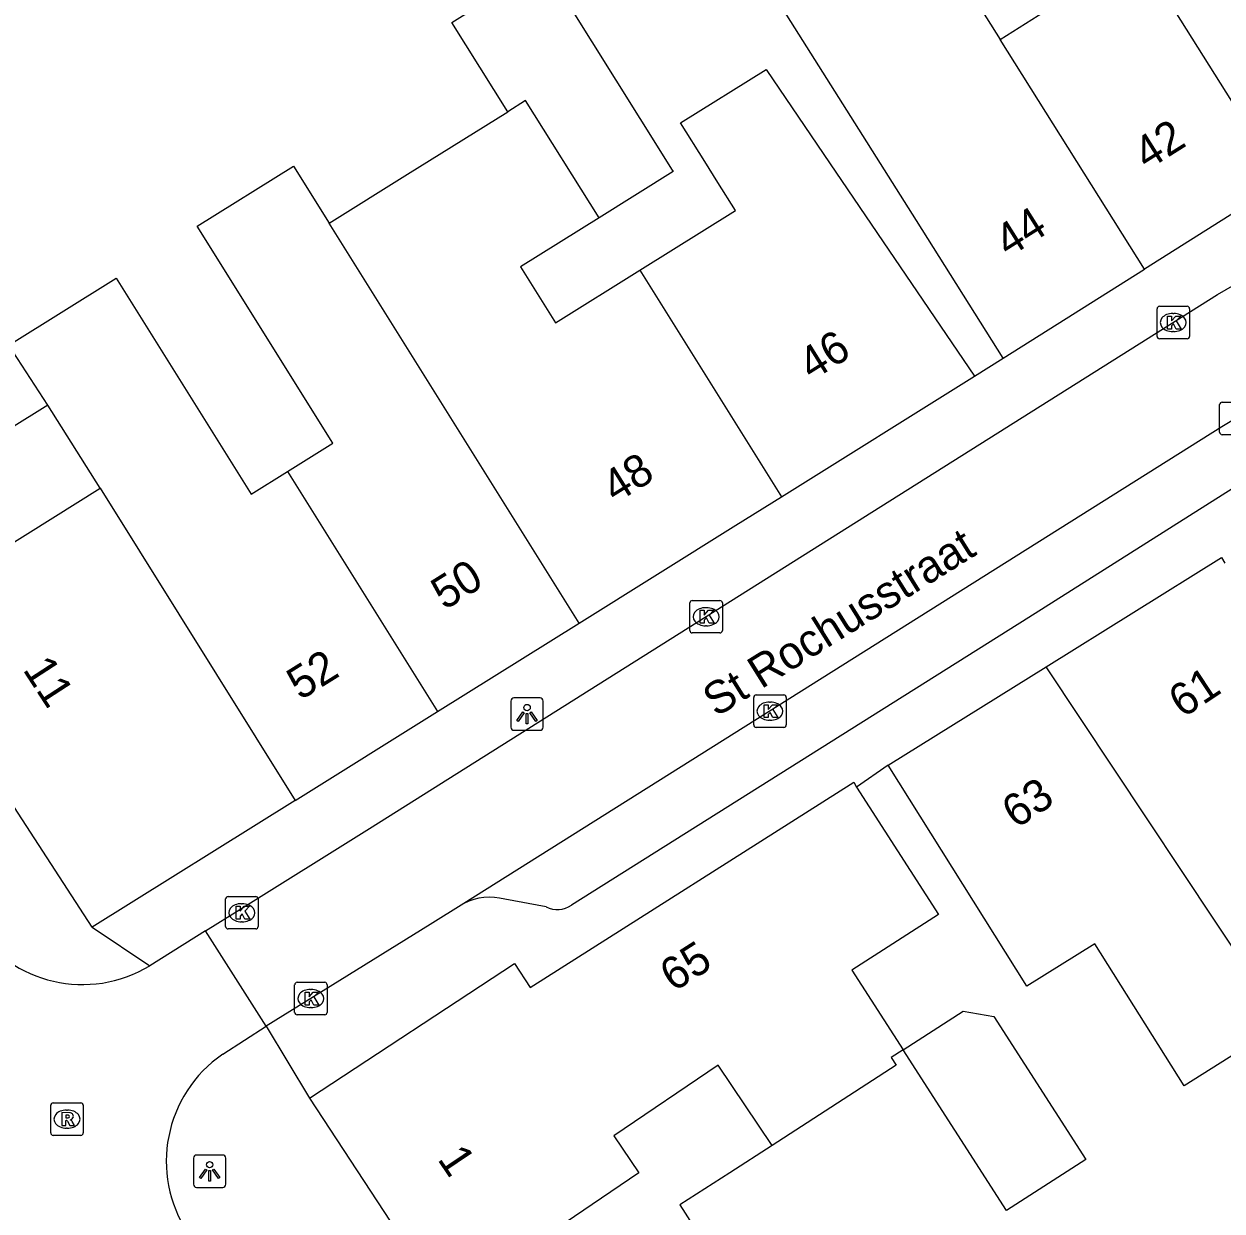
# Model space of a CAD drawing. Extents: x 161801 to 162379, y 382315 to 382832.
# Drawn here: x 161942.5 to 161979.42, y 382498.82 to 382535.41 of the extents above; entities that cross this region are included whole.
import ezdxf

# ---------------------------------------------------------------- set-up
doc = ezdxf.new("R2010")
doc.units = 0
for name, color, linetype in [('IMGEO_Kolk', 7, 'Continuous'), ('IMGEO_Lichtpunt', 7, 'Continuous'), ('IMGEO_Openbare_ruimte_label', 7, 'Continuous'), ('IMGEO_Pand', 7, 'Continuous'), ('IMGEO_Pand_nummerreeks', 7, 'Continuous'), ('IMGEO_Rijbaan_lokaal_open', 7, 'Continuous'), ('IMGEO_Rioolput', 7, 'Continuous'), ('IMGEO_Voetpad_open', 7, 'Continuous')]:
    doc.layers.add(name, color=color, linetype=linetype)

msp = doc.modelspace()

# ---------------------------------------------------------------- linework, layer by layer
at = {"layer": 'IMGEO_Kolk'}
for p, q in [((161977.413, 382525.777), (161977.413, 382526.629)), ((161977.488, 382526.703), (161978.34, 382526.703)), ((161978.414, 382526.629), (161978.414, 382525.777)), ((161977.901, 382526.483), (161977.926, 382526.483)), ((161977.924, 382525.923), (161977.899, 382525.923)), ((161978.34, 382525.703), (161977.488, 382525.703)), ((161979.341, 382522.821), (161979.341, 382523.673)), ((161979.416, 382523.747), (161980.268, 382523.747)), ((161980.268, 382522.747), (161979.416, 382522.747)), ((161963.092, 382517.636), (161963.944, 382517.636)), ((161963.017, 382516.71), (161963.017, 382517.562)), ((161963.505, 382517.416), (161963.53, 382517.416)), ((161964.018, 382517.562), (161964.018, 382516.71)), ((161963.944, 382516.636), (161963.092, 382516.636)), ((161963.528, 382516.856), (161963.503, 382516.856)), ((161965.06, 382514.726), (161965.912, 382514.726)), ((161964.985, 382513.8), (161964.985, 382514.652)), ((161965.473, 382514.506), (161965.498, 382514.506)), ((161965.986, 382514.652), (161965.986, 382513.8)), ((161965.496, 382513.946), (161965.471, 382513.946)), ((161965.912, 382513.726), (161965.06, 382513.726)), ((161948.712, 382507.587), (161948.712, 382508.439)), ((161948.787, 382508.513), (161949.639, 382508.513)), ((161949.713, 382508.439), (161949.713, 382507.587)), ((161949.2, 382508.293), (161949.225, 382508.293)), ((161949.223, 382507.733), (161949.198, 382507.733)), ((161949.639, 382507.513), (161948.787, 382507.513)), ((161950.914, 382505.87), (161951.766, 382505.87)), ((161950.839, 382504.944), (161950.839, 382505.796)), ((161951.327, 382505.65), (161951.352, 382505.65)), ((161951.84, 382505.796), (161951.84, 382504.944)), ((161951.35, 382505.09), (161951.325, 382505.09)), ((161951.766, 382504.87), (161950.914, 382504.87))]:
    msp.add_line(p, q, dxfattribs=at)
for points in [[(161977.413, 382525.777), (161977.413, 382526.629)], [(161977.488, 382526.703), (161978.34, 382526.703)], [(161978.414, 382526.629), (161978.414, 382525.777)], [(161977.734, 382526.403), (161977.857, 382526.403), (161977.857, 382526.252), (161977.987, 382526.403), (161978.151, 382526.403), (161978.005, 382526.252), (161978.158, 382526.003), (161978.006, 382526.003), (161977.921, 382526.167), (161977.857, 382526.1), (161977.857, 382526.003), (161977.734, 382526.003), (161977.734, 382526.403)], [(161978.34, 382525.703), (161977.488, 382525.703)], [(161979.341, 382522.821), (161979.341, 382523.673)], [(161979.416, 382523.747), (161980.268, 382523.747)], [(161980.268, 382522.747), (161979.416, 382522.747)], [(161963.092, 382517.636), (161963.944, 382517.636)], [(161963.017, 382516.71), (161963.017, 382517.562)], [(161963.338, 382517.336), (161963.461, 382517.336), (161963.461, 382517.185), (161963.591, 382517.336), (161963.755, 382517.336), (161963.609, 382517.185), (161963.762, 382516.936), (161963.61, 382516.936), (161963.525, 382517.1), (161963.461, 382517.033), (161963.461, 382516.936), (161963.338, 382516.936), (161963.338, 382517.336)], [(161964.018, 382517.562), (161964.018, 382516.71)], [(161963.944, 382516.636), (161963.092, 382516.636)], [(161965.06, 382514.726), (161965.912, 382514.726)], [(161964.985, 382513.8), (161964.985, 382514.652)], [(161965.306, 382514.426), (161965.429, 382514.426), (161965.429, 382514.275), (161965.559, 382514.426), (161965.723, 382514.426), (161965.577, 382514.275), (161965.73, 382514.026), (161965.578, 382514.026), (161965.493, 382514.19), (161965.429, 382514.123), (161965.429, 382514.026), (161965.306, 382514.026), (161965.306, 382514.426)], [(161965.986, 382514.652), (161965.986, 382513.8)], [(161965.912, 382513.726), (161965.06, 382513.726)], [(161948.712, 382507.587), (161948.712, 382508.439)], [(161948.787, 382508.513), (161949.639, 382508.513)], [(161949.713, 382508.439), (161949.713, 382507.587)], [(161949.033, 382508.213), (161949.156, 382508.213), (161949.156, 382508.062), (161949.286, 382508.213), (161949.45, 382508.213), (161949.304, 382508.062), (161949.457, 382507.813), (161949.305, 382507.813), (161949.22, 382507.977), (161949.156, 382507.91), (161949.156, 382507.813), (161949.033, 382507.813), (161949.033, 382508.213)], [(161949.639, 382507.513), (161948.787, 382507.513)], [(161950.914, 382505.87), (161951.766, 382505.87)], [(161950.839, 382504.944), (161950.839, 382505.796)], [(161951.16, 382505.57), (161951.283, 382505.57), (161951.283, 382505.419), (161951.413, 382505.57), (161951.577, 382505.57), (161951.431, 382505.419), (161951.584, 382505.17), (161951.432, 382505.17), (161951.347, 382505.334), (161951.283, 382505.267), (161951.283, 382505.17), (161951.16, 382505.17), (161951.16, 382505.57)], [(161951.84, 382505.796), (161951.84, 382504.944)], [(161951.766, 382504.87), (161950.914, 382504.87)]]:
    msp.add_lwpolyline(points, dxfattribs=at)
for centre, start, end in [((161977.49, 382526.627), 91.552, 178.448), ((161977.49, 382526.627), 91.552, 178.448), ((161978.338, 382526.627), 1.552, 88.448), ((161978.338, 382526.627), 1.552, 88.448), ((161977.49, 382525.779), 181.552, 268.448), ((161977.49, 382525.779), 181.552, 268.448), ((161978.338, 382525.779), 271.552, 358.448), ((161978.338, 382525.779), 271.552, 358.448), ((161979.418, 382523.671), 91.552, 178.448), ((161979.418, 382523.671), 91.552, 178.448), ((161979.418, 382522.823), 181.552, 268.448), ((161979.418, 382522.823), 181.552, 268.448), ((161963.094, 382517.56), 91.552, 178.448), ((161963.094, 382517.56), 91.552, 178.448), ((161963.942, 382517.56), 1.552, 88.448), ((161963.942, 382517.56), 1.552, 88.448), ((161963.094, 382516.712), 181.552, 268.448), ((161963.094, 382516.712), 181.552, 268.448), ((161963.942, 382516.712), 271.552, 358.448), ((161963.942, 382516.712), 271.552, 358.448), ((161965.062, 382514.65), 91.552, 178.448), ((161965.062, 382514.65), 91.552, 178.448), ((161965.91, 382514.65), 1.552, 88.448), ((161965.91, 382514.65), 1.552, 88.448), ((161965.062, 382513.802), 181.552, 268.448), ((161965.062, 382513.802), 181.552, 268.448), ((161965.91, 382513.802), 271.552, 358.448), ((161965.91, 382513.802), 271.552, 358.448), ((161948.789, 382508.437), 91.552, 178.448), ((161948.789, 382508.437), 91.552, 178.448), ((161949.637, 382508.437), 1.552, 88.448), ((161949.637, 382508.437), 1.552, 88.448), ((161948.789, 382507.589), 181.552, 268.448), ((161948.789, 382507.589), 181.552, 268.448), ((161949.637, 382507.589), 271.552, 358.448), ((161949.637, 382507.589), 271.552, 358.448), ((161950.916, 382505.794), 91.552, 178.448), ((161950.916, 382505.794), 91.552, 178.448), ((161951.764, 382505.794), 1.552, 88.448), ((161951.764, 382505.794), 1.552, 88.448), ((161950.916, 382504.946), 181.552, 268.448), ((161950.916, 382504.946), 181.552, 268.448), ((161951.764, 382504.946), 271.552, 358.448), ((161951.764, 382504.946), 271.552, 358.448)]:
    msp.add_arc(centre, 0.0765, start, end, dxfattribs=at)
for centre, major_axis, ratio, start_param, end_param in [((161977.9, 382526.203), (-0.387, 0.002), 0.722429, 4.712389, 7.853982), ((161977.925, 382526.203), (-0.39, 0.002), 0.717154, 1.570796, 4.712389), ((161963.504, 382517.136), (-0.387, 0.002), 0.722429, 4.712389, 7.853982), ((161963.529, 382517.136), (-0.39, 0.002), 0.717154, 1.570796, 4.712389), ((161965.472, 382514.226), (-0.387, 0.002), 0.722429, 4.712389, 7.853982), ((161965.497, 382514.226), (-0.39, 0.002), 0.717154, 1.570796, 4.712389), ((161949.199, 382508.013), (-0.387, 0.002), 0.722429, 4.712389, 7.853982), ((161949.224, 382508.013), (-0.39, 0.002), 0.717154, 1.570796, 4.712389), ((161951.326, 382505.37), (-0.387, 0.002), 0.722429, 4.712389, 7.853982), ((161951.351, 382505.37), (-0.39, 0.002), 0.717154, 1.570796, 4.712389)]:
    msp.add_ellipse(centre, major_axis=major_axis, ratio=ratio, start_param=start_param, end_param=end_param, dxfattribs=at)
at = {"layer": 'IMGEO_Lichtpunt'}
for p, q in [((161957.501, 382514.538), (161957.501, 382513.731)), ((161957.501, 382514.538), (161957.501, 382513.731)), ((161958.403, 382514.633), (161957.595, 382514.633)), ((161958.403, 382514.633), (161957.595, 382514.633)), ((161958.497, 382513.731), (161958.497, 382514.538)), ((161958.497, 382513.731), (161958.497, 382514.538)), ((161957.595, 382513.637), (161958.403, 382513.637)), ((161957.595, 382513.637), (161958.403, 382513.637)), ((161947.721, 382500.451), (161947.721, 382499.644)), ((161947.721, 382500.451), (161947.721, 382499.644)), ((161948.623, 382500.546), (161947.815, 382500.546)), ((161948.623, 382500.546), (161947.815, 382500.546)), ((161948.717, 382499.644), (161948.717, 382500.451)), ((161948.717, 382499.644), (161948.717, 382500.451)), ((161947.815, 382499.55), (161948.623, 382499.55)), ((161947.815, 382499.55), (161948.623, 382499.55))]:
    msp.add_line(p, q, dxfattribs=at)
for points in [[(161957.875, 382514.202), (161957.914, 382514.174), (161957.726, 382513.912), (161957.688, 382513.939), (161957.875, 382514.202)], [(161957.977, 382514.154), (161958.024, 382514.154), (161958.024, 382513.832), (161957.977, 382513.832), (161957.977, 382514.154)], [(161958.087, 382514.174), (161958.125, 382514.201), (161958.312, 382513.939), (161958.273, 382513.911), (161958.087, 382514.174)], [(161948.095, 382500.115), (161948.134, 382500.087), (161947.946, 382499.825), (161947.908, 382499.852), (161948.095, 382500.115)], [(161948.197, 382500.067), (161948.244, 382500.067), (161948.244, 382499.745), (161948.197, 382499.745), (161948.197, 382500.067)], [(161948.307, 382500.087), (161948.345, 382500.114), (161948.532, 382499.852), (161948.493, 382499.824), (161948.307, 382500.087)]]:
    msp.add_lwpolyline(points, dxfattribs=at)
for centre in [(161958, 382514.336), (161948.22, 382500.249)]:
    msp.add_circle(centre, 0.0994, dxfattribs=at)
for centre, start, end in [((161957.595, 382514.538), 90, 180), ((161957.595, 382514.538), 90, 180), ((161958.403, 382514.538), 0, 90), ((161958.403, 382514.538), 0, 90), ((161957.595, 382513.731), 180, 270), ((161957.595, 382513.731), 180, 270), ((161958.403, 382513.731), 270, 0), ((161958.403, 382513.731), 270, 360), ((161947.815, 382500.451), 90, 180), ((161947.815, 382500.451), 90, 180), ((161948.623, 382500.451), 0, 90), ((161948.623, 382500.451), 0, 90), ((161947.815, 382499.644), 180, 270), ((161947.815, 382499.644), 180, 270), ((161948.623, 382499.644), 270, 0), ((161948.623, 382499.644), 270, 360)]:
    msp.add_arc(centre, 0.0946, start, end, dxfattribs=at)
at = {"layer": 'IMGEO_Pand'}
for points in [[(161972.576, 382534.922), (161973.948, 382535.786), (161969.438, 382542.947), (161972.324, 382544.765)], [(161972.324, 382544.765), (161981.283, 382530.533)], [(161972.67, 382525.109), (161970, 382529.349), (161964.109, 382538.701), (161963.728, 382539.307), (161963.163, 382540.205), (161967.521, 382542.95), (161972.576, 382534.922)], [(161957.403, 382532.702), (161955.683, 382535.455), (161958.521, 382537.228), (161962.218, 382531.312), (161962.454, 382530.934), (161962.501, 382530.857), (161960.218, 382529.43)], [(161977.027, 382527.853), (161972.576, 382534.922)], [(161961.474, 382527.819), (161964.419, 382529.659), (161963.882, 382530.519), (161963.477, 382531.167), (161962.732, 382532.36), (161965.364, 382534.004), (161967.149, 382531.378), (161968.978, 382528.687), (161971.789, 382524.552)], [(161960.218, 382529.43), (161957.957, 382533.048), (161957.403, 382532.702)], [(161951.903, 382529.267), (161954.317, 382530.775), (161957.403, 382532.702)], [(161950.621, 382521.611), (161952.016, 382522.483), (161947.837, 382529.173), (161950.804, 382531.026), (161951.903, 382529.267)], [(161981.283, 382530.533), (161977.027, 382527.853)], [(161959.604, 382516.94), (161951.903, 382529.267)], [(161960.218, 382529.43), (161957.801, 382527.921), (161958.877, 382526.197), (161961.474, 382527.819)], [(161961.474, 382527.819), (161965.837, 382520.834)], [(161972.67, 382525.109), (161977.027, 382527.853)], [(161942.03, 382525.503), (161945.338, 382527.569), (161949.498, 382520.91), (161950.621, 382521.611)], [(161943.233, 382523.653), (161942.03, 382525.503)], [(161965.837, 382520.834), (161971.789, 382524.552)], [(161943.233, 382523.653), (161939.538, 382521.355)], [(161944.848, 382521.101), (161943.233, 382523.653)], [(161939.538, 382521.355), (161941.143, 382518.786), (161944.848, 382521.101)], [(161950.621, 382521.611), (161955.242, 382514.214)], [(161944.848, 382521.101), (161950.859, 382511.476)], [(161959.604, 382516.94), (161964.429, 382519.954), (161965.837, 382520.834)], [(161944.597, 382507.564), (161936.739, 382519.665)], [(161974, 382515.595), (161979.401, 382518.966), (161979.504, 382518.791)], [(161955.242, 382514.214), (161959.604, 382516.94)], [(161969.132, 382512.557), (161974, 382515.595)], [(161981.3, 382504.598), (161974, 382515.595)], [(161950.859, 382511.476), (161955.242, 382514.214)], [(161981.3, 382504.598), (161978.244, 382502.682), (161975.499, 382507.059), (161973.405, 382505.746), (161969.132, 382512.557)], [(161951.298, 382502.303), (161957.613, 382506.446), (161958.095, 382505.71), (161968.068, 382512.042), (161968.153, 382511.883)], [(161968.153, 382511.883), (161970.679, 382507.958), (161968.012, 382506.242), (161969.588, 382503.791)], [(161950.859, 382511.476), (161944.597, 382507.564)], [(161969.588, 382503.791), (161971.438, 382504.982), (161972.384, 382504.813), (161975.217, 382500.411), (161972.775, 382498.839), (161969.588, 382503.791)], [(161969.588, 382503.791), (161969.221, 382503.555), (161969.377, 382503.313), (161965.555, 382500.845)], [(161965.555, 382500.845), (161963.889, 382503.312), (161960.672, 382501.141), (161961.443, 382500.001), (161955.47, 382495.94)], [(161951.298, 382502.303), (161955.47, 382495.94)], [(161965.555, 382500.845), (161964.247, 382500), (161962.71, 382499.007), (161965.896, 382494.027)]]:
    msp.add_lwpolyline(points, dxfattribs=at)
at = {"layer": 'IMGEO_Rijbaan_lokaal_open'}
for points in [[(161948.095, 382507.457), (161949.145, 382508.117), (161953.15, 382510.607), (161979.276, 382527.063), (161985.491, 382530.651), (161991.203, 382533.931), (161998.314, 382537.876)], [(161996.967, 382533.235), (161986.125, 382527.031), (161979.411, 382522.988), (161956.057, 382508.297)], [(161956.057, 382508.297), (161955.014, 382507.648), (161949.963, 382504.519)], [(161948.095, 382507.457), (161946.38, 382506.38)], [(161949.963, 382504.519), (161948.095, 382507.457)], [(161948.623, 382503.653), (161949.963, 382504.519)]]:
    msp.add_lwpolyline(points, dxfattribs=at)
for centre, radius, start, end in [((161944.304, 382509.822), 4.02, 213.081, 301.0958), ((161950.883, 382500.352), 4, 124.3944, 213.4503)]:
    msp.add_arc(centre, radius, start, end, dxfattribs=at)
at = {"layer": 'IMGEO_Rioolput'}
for p, q in [((161943.398, 382502.153), (161944.25, 382502.153)), ((161943.323, 382501.227), (161943.323, 382502.079)), ((161943.811, 382501.933), (161943.836, 382501.933)), ((161944.324, 382502.079), (161944.324, 382501.227)), ((161944.25, 382501.153), (161943.398, 382501.153)), ((161943.834, 382501.373), (161943.809, 382501.373))]:
    msp.add_line(p, q, dxfattribs=at)
for points in [[(161943.398, 382502.153), (161944.25, 382502.153)], [(161943.323, 382501.227), (161943.323, 382502.079)], [(161943.912, 382501.851), (161943.66, 382501.853), (161943.66, 382501.453)], [(161943.838, 382501.772), (161943.784, 382501.772), (161943.784, 382501.691)], [(161944.324, 382502.079), (161944.324, 382501.227)], [(161943.66, 382501.453), (161943.784, 382501.453), (161943.784, 382501.615), (161943.795, 382501.615)], [(161943.784, 382501.691), (161943.836, 382501.691)], [(161943.842, 382501.586), (161943.913, 382501.453), (161944.053, 382501.453), (161943.988, 382501.579)], [(161944.25, 382501.153), (161943.398, 382501.153)]]:
    msp.add_lwpolyline(points, dxfattribs=at)
for centre, radius, start, end in [((161943.4, 382502.077), 0.0765, 91.552, 178.448), ((161943.4, 382502.077), 0.0765, 91.552, 178.448), ((161944.248, 382502.077), 0.0765, 1.552, 88.448), ((161944.248, 382502.077), 0.0765, 1.552, 88.448), ((161943.844, 382501.676), 0.0964, 77.0061, 93.1865), ((161943.858, 382501.733), 0.0378, 276.6634, 79.6772), ((161943.911, 382501.741), 0.109, 350.3612, 89.416), ((161943.794, 382501.562), 0.0533, 26.0293, 88.6989), ((161943.82, 382501.88), 0.19, 274.7715, 282.9687), ((161943.909, 382501.741), 0.112, 277.5842, 350.9817), ((161943.893, 382501.526), 0.108, 29.5134, 73.7905), ((161943.4, 382501.229), 0.0765, 181.552, 268.448), ((161943.4, 382501.229), 0.0765, 181.552, 268.448), ((161944.248, 382501.229), 0.0765, 271.552, 358.448), ((161944.248, 382501.229), 0.0765, 271.552, 358.448)]:
    msp.add_arc(centre, radius, start, end, dxfattribs=at)
for centre, major_axis, ratio, start_param, end_param in [((161943.81, 382501.653), (-0.387, 0.002), 0.722429, 4.712389, 7.853982), ((161943.835, 382501.653), (-0.39, 0.002), 0.717154, 1.570796, 4.712389)]:
    msp.add_ellipse(centre, major_axis=major_axis, ratio=ratio, start_param=start_param, end_param=end_param, dxfattribs=at)
at = {"layer": 'IMGEO_Voetpad_open'}
for points in [[(161995.101, 382530.091), (161987.08, 382525.499), (161983.445, 382523.349), (161980.229, 382521.393), (161973.467, 382517.114), (161959.365, 382508.249)], [(161971.789, 382524.552), (161972.67, 382525.109)], [(161969.132, 382512.557), (161968.153, 382511.883)], [(161958.592, 382508.194), (161957.313, 382508.432)], [(161944.597, 382507.564), (161946.38, 382506.38)], [(161949.963, 382504.519), (161951.298, 382502.303)]]:
    msp.add_lwpolyline(points, dxfattribs=at)
for centre, radius, start, end in [((161956.857, 382506.76), 1.733, 74.7584, 117.5112), ((161958.933, 382508.856), 0.745, 242.7126, 305.427)]:
    msp.add_arc(centre, radius, start, end, dxfattribs=at)

# ---------------------------------------------------------------- texts
at = {"layer": 'IMGEO_Openbare_ruimte_label'}
msp.add_text('St Rochusstraat', height=1, rotation=32.0054, dxfattribs=at).set_placement((161963.828, 382514.027))
at = {"layer": 'IMGEO_Pand_nummerreeks'}
for s, rotation, p in [('42', 32.2064, (161977.106, 382530.881)), ('44', 32.2002, (161972.83, 382528.188)), ('46', 31.994, (161966.776, 382524.392)), ('48', 31.994, (161960.726, 382520.613)), ('50', 31.9882, (161955.458, 382517.322)), ('11', 302.9964, (161942.443, 382515.508)), ('52', 31.9997, (161951.012, 382514.543)), ('61', 33.5811, (161978.208, 382513.995)), ('63', 33.5785, (161973.071, 382510.584)), ('65', 32.4122, (161962.514, 382505.555)), ('1', 303.9934, (161955.22, 382500.421))]:
    msp.add_text(s, height=1, rotation=rotation, dxfattribs=at).set_placement(p)

doc.saveas('drawing.dxf')
